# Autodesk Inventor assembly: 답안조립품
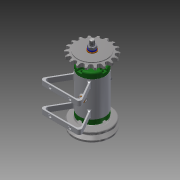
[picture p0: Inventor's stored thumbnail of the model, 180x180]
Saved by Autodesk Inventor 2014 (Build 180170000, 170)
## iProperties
Created: 2016-03
Part Number: 답안조립품
Document SubType Name: Assembly
Designer: 406-017
Author: 406-017
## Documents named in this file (14)
- C:\Users\406-017\Desktop\460307V1009\답안조립품.iam
- C:\Users\406-017\Desktop\460307V1009\부품1.ipt
- C:\Users\406-017\Desktop\460307V1009\축.ipt
- C:\Users\406-017\Desktop\460307V1009\와셔 8x17.ipt
- C:\Users\406-017\Desktop\460307V1009\키 3 x 3 x 12.ipt
- C:\Users\406-017\Desktop\460307V1009\스프링와셔 8.ipt
- C:\Users\406-017\Desktop\460307V1009\너트 M 8.ipt
- C:\Users\406-017\Desktop\460307V1009\V벨트풀리.ipt
- C:\Users\406-017\Desktop\460307V1009\스프로킷.ipt
- C:\Users\406-017\Desktop\460307V1009\니플 M 6 x 0.75.ipt
- C:\Users\406-017\Desktop\460307V1009\볼트 M 6 x 8.ipt
- C:\Users\406-017\Desktop\460307V1009\와셔 6x11.5.ipt
- C:\Users\406-017\Desktop\460307V1009\커버.ipt
- C:\Users\406-017\Desktop\460307V1009\베어링 15 x 32 x 9.ipt
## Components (3 placed, 2 different names)
1. V벨트풀리:1 — 각도:3
2. KS B 2023 6002 - 15 x 32 x 9:1
3. KS B 2023 6002 - 15 x 32 x 9:2
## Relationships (1: Angle 1)
- 각도:3 [Angle]: V벨트풀리:1
